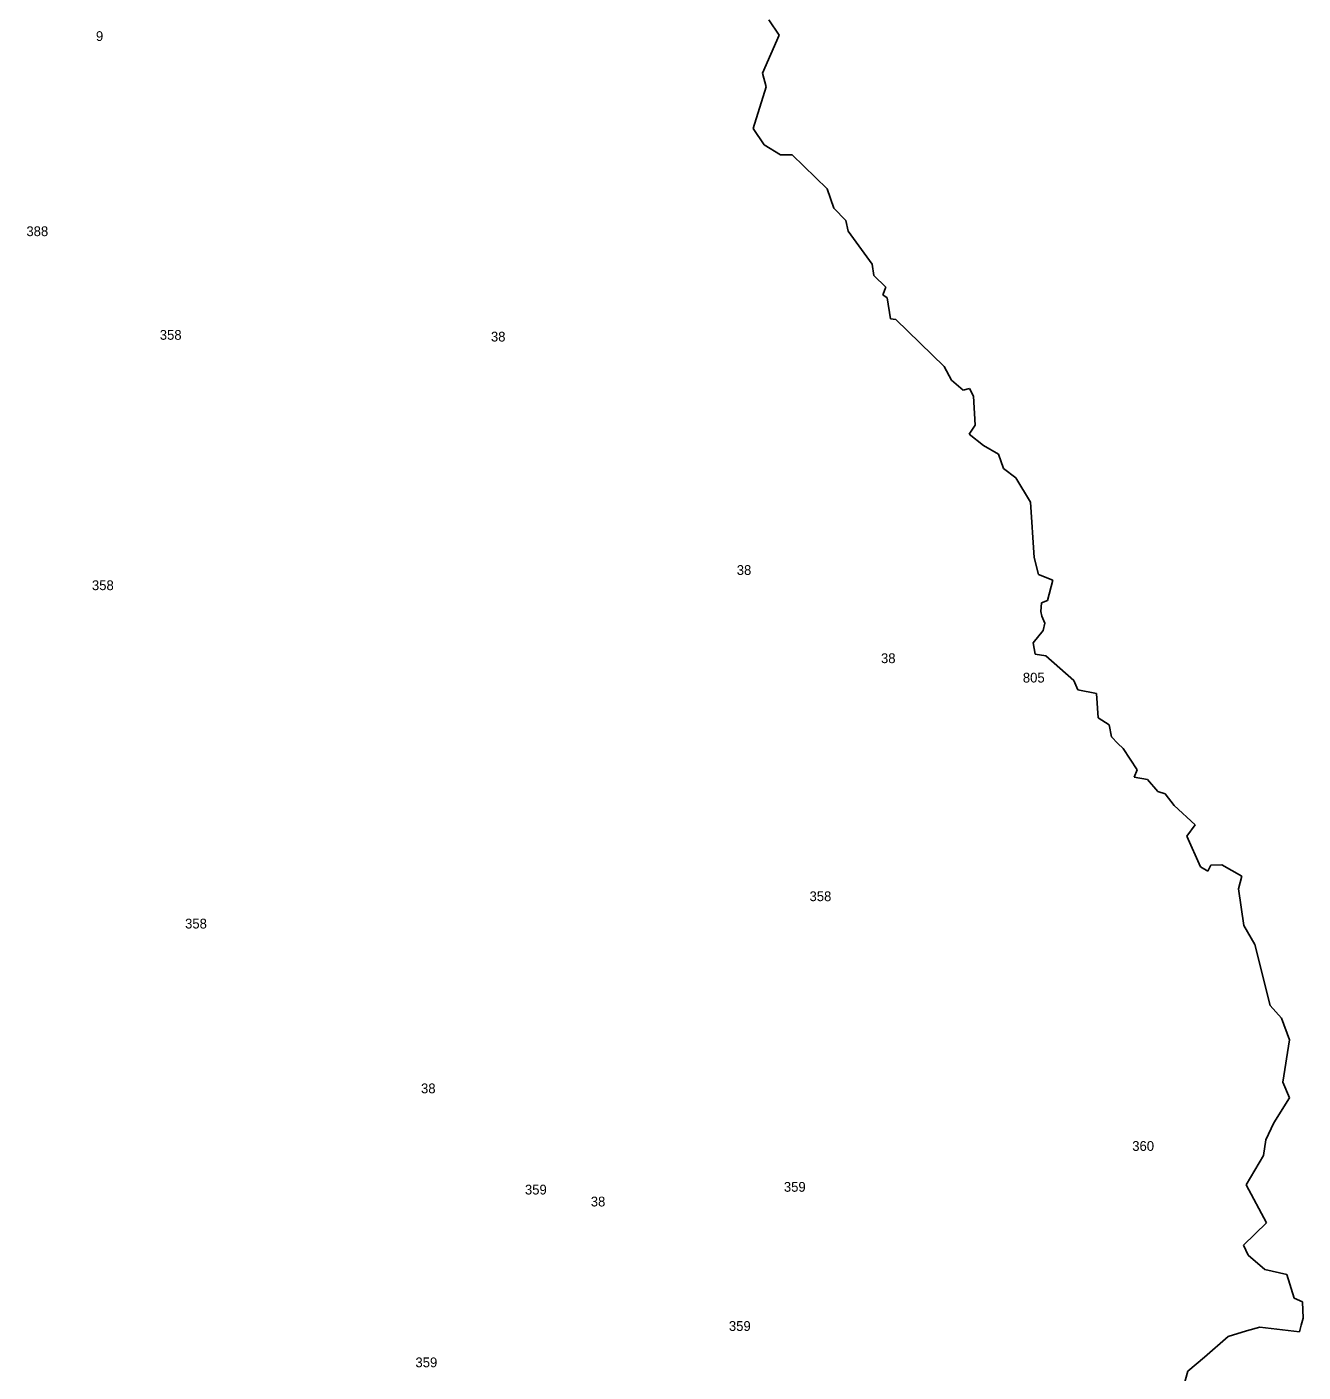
# Model space of a CAD drawing. Extents: x -782977 to -778030, y -975420 to -964838.
# Drawn here: x -780376 to -779474, y -973722 to -972772 of the extents above; entities that cross this region are included whole.
import ezdxf

# ---------------------------------------------------------------- set-up
doc = ezdxf.new("R2010")
doc.units = 0
doc.layers.add('Vrstva 13', color=7, linetype='Continuous')
doc.layers.add('Vrstva 24', color=7, linetype='Continuous')

msp = doc.modelspace()

# ---------------------------------------------------------------- linework, layer by layer
at = {"layer": 'Vrstva 13'}
for p, q in [((-779843.99, -972777.35), (-779851.17, -972766.57)), ((-779855.69, -972804.16), (-779843.99, -972777.35)), ((-779853.05, -972813.88), (-779855.69, -972804.16)), ((-779862.36, -972843.33), (-779853.05, -972813.88)), ((-779854.44, -972854.77), (-779862.36, -972843.33)), ((-779843.06, -972861.92), (-779854.44, -972854.77)), ((-779834.77, -972861.87), (-779843.06, -972861.92)), ((-779810.11, -972885.99), (-779834.77, -972861.87)), ((-779805.28, -972899.63), (-779810.11, -972885.99)), ((-779796.93, -972908.23), (-779805.28, -972899.63)), ((-779795.2, -972915.77), (-779796.93, -972908.23)), ((-779778.15, -972939.08), (-779795.2, -972915.77)), ((-779776.96, -972947.14), (-779778.15, -972939.08)), ((-779768.54, -972955.36), (-779776.96, -972947.14)), ((-779770.6, -972960.85), (-779768.54, -972955.36)), ((-779767.6, -972962.79), (-779770.6, -972960.85)), ((-779765.29, -972977.78), (-779767.6, -972962.79)), ((-779761.42, -972978.19), (-779765.29, -972977.78)), ((-779727.24, -973011.4), (-779761.42, -972978.19)), ((-779722.15, -973021.12), (-779727.24, -973011.4)), ((-779713.99, -973028.09), (-779722.15, -973021.12)), ((-779709.49, -973027.05), (-779713.99, -973028.09)), ((-779706.67, -973032.31), (-779709.49, -973027.05)), ((-779705.39, -973052.73), (-779706.67, -973032.31)), ((-779709.56, -973059.29), (-779705.39, -973052.73)), ((-779699.64, -973067.13), (-779709.56, -973059.29)), ((-779689.01, -973073.38), (-779699.64, -973067.13)), ((-779685.39, -973083.55), (-779689.01, -973073.38)), ((-779676.65, -973089.96), (-779685.39, -973083.55)), ((-779666.37, -973107.26), (-779676.65, -973089.96)), ((-779663.65, -973146.26), (-779666.37, -973107.26)), ((-779660.71, -973158.21), (-779663.65, -973146.26)), ((-779650.64, -973162.44), (-779660.71, -973158.21)), ((-779654.35, -973176.69), (-779650.64, -973162.44)), ((-779659.03, -973184.47), (-779658.62, -973178.36)), ((-779658.37, -973187.72), (-779659.03, -973184.47)), ((-779658.62, -973178.36), (-779654.35, -973176.69)), ((-779656.23, -973192.81), (-779658.37, -973187.72)), ((-779657.35, -973198), (-779656.23, -973192.81)), ((-779664.31, -973206.6), (-779657.35, -973198)), ((-779663.09, -973214.54), (-779664.31, -973206.6)), ((-779655.41, -973215.71), (-779663.09, -973214.54)), ((-779635.73, -973233.31), (-779655.41, -973215.71)), ((-779632.84, -973239.88), (-779635.73, -973233.31)), ((-779619.72, -973242.47), (-779632.84, -973239.88)), ((-779618.5, -973259.62), (-779619.72, -973242.47)), ((-779610.62, -973264.55), (-779618.5, -973259.62)), ((-779609.01, -973272.92), (-779610.62, -973264.55)), ((-779604.52, -973277.62), (-779609.01, -973272.92)), ((-779600.75, -973281.28), (-779604.52, -973277.62)), ((-779591.03, -973296.41), (-779600.75, -973281.28)), ((-779593.04, -973301.37), (-779591.03, -973296.41)), ((-779583.74, -973303.03), (-779593.04, -973301.37)), ((-779576.27, -973311.63), (-779583.74, -973303.03)), ((-779571.13, -973313.36), (-779576.27, -973311.63)), ((-779564.72, -973321.44), (-779571.13, -973313.36)), ((-779550.03, -973335.08), (-779564.72, -973321.44)), ((-779555.93, -973343.12), (-779550.03, -973335.08)), ((-779546.16, -973364.79), (-779555.93, -973343.12)), ((-779541.07, -973367.99), (-779546.16, -973364.79)), ((-779538.84, -973363.67), (-779541.07, -973367.99)), ((-779531.01, -973363.51), (-779538.84, -973363.67)), ((-779516.97, -973371.4), (-779531.01, -973363.51)), ((-779519.36, -973380.35), (-779516.97, -973371.4)), ((-779515.61, -973406.29), (-779519.36, -973380.35)), ((-779507.83, -973419.77), (-779515.61, -973406.29)), ((-779497.04, -973462.76), (-779507.83, -973419.77)), ((-779488.85, -973471.61), (-779497.04, -973462.76)), ((-779483.31, -973487.07), (-779488.85, -973471.61)), ((-779488.06, -973516.95), (-779483.31, -973487.07)), ((-779483.37, -973527.98), (-779488.06, -973516.95)), ((-779494.31, -973545.69), (-779483.37, -973527.98)), ((-779499.95, -973557.69), (-779494.31, -973545.69)), ((-779501.58, -973568.68), (-779499.95, -973557.69)), ((-779513.99, -973589.53), (-779501.58, -973568.68)), ((-779499.59, -973616.24), (-779513.99, -973589.53)), ((-779515.82, -973632.17), (-779499.59, -973616.24)), ((-779512.59, -973639.16), (-779515.82, -973632.17)), ((-779500.79, -973649.24), (-779512.59, -973639.16)), ((-779485.13, -973652.8), (-779500.79, -973649.24)), ((-779480.03, -973669.57), (-779485.13, -973652.8)), ((-779474.17, -973672.2), (-779480.03, -973669.57)), ((-779473.66, -973683.55), (-779474.17, -973672.2)), ((-779476.31, -973693.26), (-779474.93, -973688.48)), ((-779474.93, -973688.48), (-779473.66, -973683.55)), ((-779543.38, -973711.11), (-779526.55, -973696.62)), ((-779526.55, -973696.62), (-779513.68, -973692.5)), ((-779513.68, -973692.5), (-779504.22, -973690.11)), ((-779504.22, -973690.11), (-779476.31, -973693.26)), ((-779555.15, -973721), (-779543.38, -973711.11)), ((-779559.52, -973737.08), (-779555.15, -973721))]:
    msp.add_line(p, q, dxfattribs=at)

# ---------------------------------------------------------------- texts
at = {"layer": 'Vrstva 24'}
for s, p in [('9', (-780326.767, -972781.472)), ('388', (-780375.912, -972919.312)), ('358', (-780281.652, -972992.522)), ('38', (-780047.626, -972993.742)), ('38', (-779873.896, -973158.632)), ('358', (-780329.602, -973169.372)), ('38', (-779771.976, -973220.932)), ('805', (-779671.724, -973234.642)), ('358', (-779822.482, -973389.072)), ('358', (-780263.772, -973408.382)), ('38', (-780097.026, -973524.782)), ('360', (-779594.411, -973565.482)), ('359', (-780023.599, -973596.282)), ('359', (-779840.609, -973594.352)), ('38', (-779977.066, -973604.722)), ('359', (-779879.449, -973692.632)), ('359', (-780100.979, -973718.322))]:
    msp.add_text(s, height=6.912, dxfattribs=at).set_placement(p)

doc.saveas('drawing.dxf')
